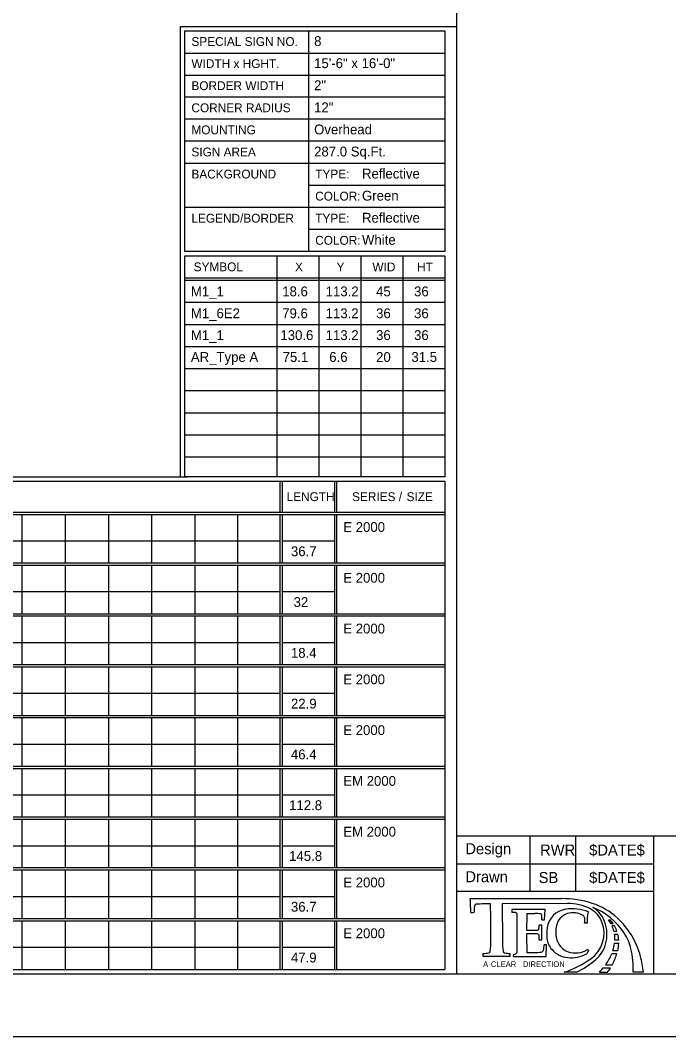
# Model space of a CAD drawing. Extents: x 2149934 to 2150188, y 145114 to 145238.
# Drawn here: x 2150112.6 to 2150146.6, y 145114.1 to 145167.4 of the extents above; entities that cross this region are included whole.
import ezdxf

# ---------------------------------------------------------------- set-up
doc = ezdxf.new("R2010")
doc.units = 0
for name, color, linetype in [('BORDER', 7, 'Continuous'), ('DATE', 7, 'Continuous'), ('GSSHT', 7, 'Continuous'), ('Level 1', 7, 'Continuous'), ('PDF', 7, 'Continuous'), ('TEC LOGO', 7, 'Continuous')]:
    doc.layers.add(name, color=color, linetype=linetype)

msp = doc.modelspace()

# ---------------------------------------------------------------- linework, layer by layer
at = {"layer": 'BORDER'}
for p, q in [((2150171.536, 145124.606), (2150135.447, 145124.606)), ((2150135.447, 145124.606), (2150135.447, 145117.388)), ((2150139.297, 145124.606), (2150139.297, 145121.719)), ((2150141.703, 145121.719), (2150141.703, 145124.606)), ((2150145.8, 145117.359), (2150145.8, 145124.577)), ((2150135.447, 145123.162), (2150145.8, 145123.162)), ((2150135.447, 145121.719), (2150145.8, 145121.719)), ((2150017.557, 145117.388), (2150171.536, 145117.388)), ((2150010.458, 145114.088), (2150174.061, 145114.088))]:
    msp.add_line(p, q, dxfattribs=at)
at = {"layer": 'Level 1'}
for p, q in [((2150135.447, 145216.512), (2150135.447, 145124.606)), ((2150120.969, 145167.112), (2150135.447, 145167.112)), ((2150127.694, 145166.88), (2150127.694, 145155.308)), ((2150121.201, 145165.721), (2150134.843, 145165.721)), ((2150121.201, 145164.561), (2150134.843, 145164.561)), ((2150121.201, 145163.425), (2150134.843, 145163.425)), ((2150121.201, 145162.265), (2150134.843, 145162.265)), ((2150121.201, 145161.106), (2150134.843, 145161.106)), ((2150121.201, 145159.946), (2150134.843, 145159.946)), ((2150127.694, 145158.787), (2150134.843, 145158.787)), ((2150121.201, 145157.627), (2150134.843, 145157.627)), ((2150127.694, 145156.468), (2150134.843, 145156.468)), ((2150121.201, 145143.476), (2150121.201, 145155.077)), ((2150121.201, 145155.077), (2150134.843, 145155.077)), ((2150126.031, 145155.071), (2150126.031, 145153.912)), ((2150128.234, 145155.071), (2150128.234, 145153.912)), ((2150130.437, 145155.071), (2150130.437, 145153.912)), ((2150132.64, 145155.071), (2150132.64, 145153.912)), ((2150134.843, 145155.077), (2150134.843, 145143.476)), ((2150121.201, 145153.912), (2150134.843, 145153.912)), ((2150121.201, 145153.796), (2150134.843, 145153.796)), ((2150126.031, 145153.912), (2150126.031, 145143.476)), ((2150128.234, 145153.912), (2150128.234, 145143.476)), ((2150130.437, 145153.912), (2150130.437, 145143.476)), ((2150132.64, 145153.912), (2150132.64, 145143.476)), ((2150121.201, 145152.636), (2150134.843, 145152.636)), ((2150121.201, 145151.477), (2150134.843, 145151.477)), ((2150121.201, 145150.317), (2150134.843, 145150.317)), ((2150121.201, 145149.158), (2150134.843, 145149.158)), ((2150121.201, 145147.998), (2150134.843, 145147.998)), ((2150121.201, 145146.839), (2150134.843, 145146.839)), ((2150121.201, 145145.679), (2150134.843, 145145.679)), ((2150121.201, 145144.52), (2150134.843, 145144.52)), ((2150076.316, 145143.476), (2150121.342, 145143.476)), ((2150076.548, 145143.244), (2150134.843, 145143.244)), ((2150134.843, 145143.476), (2150121.201, 145143.476)), ((2150126.185, 145143.244), (2150126.185, 145141.621)), ((2150126.301, 145143.244), (2150126.301, 145141.621)), ((2150129.048, 145143.244), (2150129.048, 145141.621)), ((2150129.164, 145143.244), (2150129.164, 145141.621)), ((2150134.843, 145143.244), (2150134.843, 145117.62)), ((2150076.548, 145141.621), (2150134.843, 145141.621)), ((2150076.548, 145141.505), (2150134.843, 145141.505)), ((2150112.654, 145141.505), (2150112.654, 145138.954)), ((2150114.927, 145141.505), (2150114.927, 145138.954)), ((2150117.199, 145141.505), (2150117.199, 145138.954)), ((2150119.449, 145141.505), (2150119.449, 145138.954)), ((2150121.721, 145141.505), (2150121.721, 145138.954)), ((2150123.97, 145141.505), (2150123.97, 145138.954)), ((2150126.185, 145141.505), (2150126.185, 145138.954)), ((2150126.301, 145141.505), (2150126.301, 145138.954)), ((2150129.048, 145141.505), (2150129.048, 145138.954)), ((2150129.164, 145141.505), (2150129.164, 145138.954)), ((2150076.548, 145140.114), (2150126.185, 145140.114)), ((2150126.301, 145140.114), (2150129.048, 145140.114)), ((2150076.548, 145138.954), (2150134.843, 145138.954)), ((2150076.548, 145138.838), (2150134.843, 145138.838)), ((2150112.654, 145138.838), (2150112.654, 145136.288)), ((2150114.927, 145138.838), (2150114.927, 145136.288)), ((2150117.199, 145138.838), (2150117.199, 145136.288)), ((2150119.449, 145138.838), (2150119.449, 145136.288)), ((2150121.721, 145138.838), (2150121.721, 145136.288)), ((2150123.97, 145138.838), (2150123.97, 145136.288)), ((2150126.185, 145138.838), (2150126.185, 145136.288)), ((2150126.301, 145138.838), (2150126.301, 145136.288)), ((2150129.048, 145138.838), (2150129.048, 145136.288)), ((2150129.164, 145138.838), (2150129.164, 145136.288)), ((2150076.548, 145137.447), (2150126.185, 145137.447)), ((2150126.301, 145137.447), (2150129.048, 145137.447)), ((2150076.548, 145136.288), (2150134.843, 145136.288)), ((2150076.548, 145136.172), (2150134.843, 145136.172)), ((2150112.654, 145136.172), (2150112.654, 145133.621)), ((2150114.927, 145136.172), (2150114.927, 145133.621)), ((2150117.199, 145136.172), (2150117.199, 145133.621)), ((2150119.449, 145136.172), (2150119.449, 145133.621)), ((2150121.721, 145136.172), (2150121.721, 145133.621)), ((2150123.97, 145136.172), (2150123.97, 145133.621)), ((2150126.185, 145136.172), (2150126.185, 145133.621)), ((2150126.301, 145136.172), (2150126.301, 145133.621)), ((2150129.048, 145136.172), (2150129.048, 145133.621)), ((2150129.164, 145136.172), (2150129.164, 145133.621)), ((2150076.548, 145134.78), (2150126.185, 145134.78)), ((2150126.301, 145134.78), (2150129.048, 145134.78)), ((2150076.548, 145133.621), (2150134.843, 145133.621)), ((2150076.548, 145133.505), (2150134.843, 145133.505)), ((2150112.654, 145133.505), (2150112.654, 145130.954)), ((2150114.927, 145133.505), (2150114.927, 145130.954)), ((2150117.199, 145133.505), (2150117.199, 145130.954)), ((2150119.449, 145133.505), (2150119.449, 145130.954)), ((2150121.721, 145133.505), (2150121.721, 145130.954)), ((2150123.97, 145133.505), (2150123.97, 145130.954)), ((2150126.185, 145133.505), (2150126.185, 145130.954)), ((2150126.301, 145133.505), (2150126.301, 145130.954)), ((2150129.048, 145133.505), (2150129.048, 145130.954)), ((2150129.164, 145133.505), (2150129.164, 145130.954)), ((2150076.548, 145132.113), (2150126.185, 145132.113)), ((2150126.301, 145132.113), (2150129.048, 145132.113)), ((2150076.548, 145130.954), (2150134.843, 145130.954)), ((2150076.548, 145130.838), (2150134.843, 145130.838)), ((2150112.654, 145130.838), (2150112.654, 145128.287)), ((2150114.927, 145130.838), (2150114.927, 145128.287)), ((2150117.199, 145130.838), (2150117.199, 145128.287)), ((2150119.449, 145130.838), (2150119.449, 145128.287)), ((2150121.721, 145130.838), (2150121.721, 145128.287)), ((2150123.97, 145130.838), (2150123.97, 145128.287)), ((2150126.185, 145130.838), (2150126.185, 145128.287)), ((2150126.301, 145130.838), (2150126.301, 145128.287)), ((2150129.048, 145130.838), (2150129.048, 145128.287)), ((2150129.164, 145130.838), (2150129.164, 145128.287)), ((2150076.548, 145129.447), (2150126.185, 145129.447)), ((2150126.301, 145129.447), (2150129.048, 145129.447)), ((2150076.548, 145128.287), (2150134.843, 145128.287)), ((2150076.548, 145128.171), (2150134.843, 145128.171)), ((2150112.654, 145128.171), (2150112.654, 145125.62)), ((2150114.927, 145128.171), (2150114.927, 145125.62)), ((2150117.199, 145128.171), (2150117.199, 145125.62)), ((2150119.449, 145128.171), (2150119.449, 145125.62)), ((2150121.721, 145128.171), (2150121.721, 145125.62)), ((2150123.97, 145128.171), (2150123.97, 145125.62)), ((2150126.185, 145128.171), (2150126.185, 145125.62)), ((2150126.301, 145128.171), (2150126.301, 145125.62)), ((2150129.048, 145128.171), (2150129.048, 145125.62)), ((2150129.164, 145128.171), (2150129.164, 145125.62)), ((2150076.548, 145126.78), (2150126.185, 145126.78)), ((2150126.301, 145126.78), (2150129.048, 145126.78)), ((2150076.548, 145125.62), (2150134.843, 145125.62)), ((2150076.548, 145125.504), (2150134.843, 145125.504)), ((2150112.654, 145125.504), (2150112.654, 145122.954)), ((2150114.927, 145125.504), (2150114.927, 145122.954)), ((2150117.199, 145125.504), (2150117.199, 145122.954)), ((2150119.449, 145125.504), (2150119.449, 145122.954)), ((2150121.721, 145125.504), (2150121.721, 145122.954)), ((2150123.97, 145125.504), (2150123.97, 145122.954)), ((2150126.185, 145125.504), (2150126.185, 145122.954)), ((2150126.301, 145125.504), (2150126.301, 145122.954)), ((2150129.048, 145125.504), (2150129.048, 145122.954)), ((2150129.164, 145125.504), (2150129.164, 145122.954)), ((2150076.548, 145124.113), (2150126.185, 145124.113)), ((2150126.301, 145124.113), (2150129.048, 145124.113)), ((2150134.843, 145122.954), (2150076.548, 145122.954)), ((2150076.548, 145122.838), (2150134.843, 145122.838)), ((2150112.654, 145122.838), (2150112.654, 145120.287)), ((2150114.927, 145122.838), (2150114.927, 145120.287)), ((2150117.199, 145122.838), (2150117.199, 145120.287)), ((2150119.449, 145122.838), (2150119.449, 145120.287)), ((2150121.721, 145122.838), (2150121.721, 145120.287)), ((2150123.97, 145122.838), (2150123.97, 145120.287)), ((2150126.185, 145122.838), (2150126.185, 145120.287)), ((2150126.301, 145122.838), (2150126.301, 145120.287)), ((2150129.048, 145122.838), (2150129.048, 145120.287)), ((2150129.164, 145122.838), (2150129.164, 145120.287)), ((2150076.548, 145121.446), (2150126.185, 145121.446)), ((2150126.301, 145121.446), (2150129.048, 145121.446)), ((2150076.548, 145120.287), (2150134.843, 145120.287)), ((2150076.548, 145120.171), (2150134.843, 145120.171)), ((2150112.654, 145120.171), (2150112.654, 145117.62)), ((2150114.927, 145120.171), (2150114.927, 145117.62)), ((2150117.199, 145120.171), (2150117.199, 145117.62)), ((2150119.449, 145120.171), (2150119.449, 145117.62)), ((2150121.721, 145120.171), (2150121.721, 145117.62)), ((2150123.97, 145120.171), (2150123.97, 145117.62)), ((2150126.185, 145120.171), (2150126.185, 145117.62)), ((2150126.301, 145120.171), (2150126.301, 145117.62)), ((2150129.048, 145120.171), (2150129.048, 145117.62)), ((2150129.164, 145120.171), (2150129.164, 145117.62)), ((2150076.548, 145118.779), (2150126.185, 145118.779)), ((2150126.301, 145118.779), (2150129.048, 145118.779)), ((2150076.548, 145117.62), (2150134.843, 145117.62))]:
    msp.add_line(p, q, dxfattribs=at)
msp.add_lwpolyline([(2150120.969, 145143.476), (2150120.969, 145167.112)], dxfattribs=at)
msp.add_lwpolyline([(2150121.201, 145166.88), (2150134.843, 145166.88), (2150134.843, 145155.308), (2150121.201, 145155.308)], close=True, dxfattribs=at)
at = {"layer": 'PDF'}
msp.add_lwpolyline([(2150010.458, 145114.088), (2150174.061, 145114.088), (2150174.061, 145219.948), (2150010.458, 145219.948)], close=True, dxfattribs=at)
at = {"layer": 'TEC LOGO'}
for p, q in [((2150136.163, 145121.335), (2150140.955, 145121.335)), ((2150141.264, 145121.082), (2150137.847, 145121.062)), ((2150137.238, 145121.058), (2150136.905, 145121.056)), ((2150137.847, 145121.062), (2150137.86, 145119.111)), ((2150138.352, 145120.759), (2150138.349, 145120.611)), ((2150140.106, 145120.759), (2150138.352, 145120.759)), ((2150139.134, 145120.555), (2150139.56, 145120.552)), ((2150140.07, 145120.219), (2150140.106, 145120.759)), ((2150139.925, 145120.219), (2150140.07, 145120.219)), ((2150142.3, 145120.043), (2150142.168, 145120.048)), ((2150142.307, 145120.354), (2150142.3, 145120.043)), ((2150143.414, 145120.213), (2150143.504, 145120.213)), ((2150143.669, 145120.008), (2150143.554, 145120.008)), ((2150139.925, 145119.934), (2150139.778, 145119.934)), ((2150139.925, 145119.172), (2150139.925, 145119.934)), ((2150143.731, 145119.909), (2150143.606, 145119.909)), ((2150143.709, 145119.627), (2150143.862, 145119.627)), ((2150139.785, 145119.172), (2150139.925, 145119.172)), ((2150143.74, 145119.471), (2150143.909, 145119.471)), ((2150143.743, 145118.997), (2150143.958, 145118.997)), ((2150143.957, 145119.151), (2150143.755, 145119.151)), ((2150136.856, 145118.3), (2150136.856, 145118.452)), ((2150138.255, 145118.452), (2150138.255, 145118.3)), ((2150140.175, 145118.91), (2150140.043, 145118.91)), ((2150140.159, 145118.3), (2150140.175, 145118.91)), ((2150142.374, 145118.62), (2150142.288, 145118.435)), ((2150142.324, 145118.657), (2150142.374, 145118.62)), ((2150143.86, 145118.438), (2150143.591, 145118.438)), ((2150143.903, 145118.595), (2150143.65, 145118.595)), ((2150138.255, 145118.3), (2150136.856, 145118.3)), ((2150138.439, 145118.399), (2150138.43, 145118.3)), ((2150138.43, 145118.3), (2150140.159, 145118.3)), ((2150141.747, 145117.467), (2150141.099, 145117.467)), ((2150142.942, 145117.467), (2150143.375, 145117.467)), ((2150143.52, 145117.689), (2150143.126, 145117.689)), ((2150143.264, 145117.867), (2150143.623, 145117.867)), ((2150145.252, 145117.467), (2150144.714, 145117.467))]:
    msp.add_line(p, q, dxfattribs=at)
for centre, radius, start, end in [((2150129.713, 145120.639), 6.487, 359.663, 6.1563), ((2150140.955, 145116.038), 5.297, 72.2522, 90), ((2150141.28, 145118.51), 2.573, 62.4303, 90.3367), ((2150141.492, 145117.716), 3.535, 47.2839, 72.2522), ((2150136.235, 145120.976), 0.377, 264.6321, 291.5899), ((2150142.861, 145120.639), 6.487, 178.5623, 180.1181), ((2150137.218, 145120.781), 0.843, 167.5337, 178.5623), ((2150136.49, 145120.942), 0.0962, 94.698, 167.5337), ((2150136.937, 145115.493), 5.563, 90.3367, 94.698), ((2150046.46, 145119.478), 90.791, 359.77628, 0.99712), ((2150138.383, 145119.475), 1.137, 80.6874, 91.7186), ((2150138.555, 145120.525), 0.0722, 1.4011, 80.6874), ((2150222.857, 145119.533), 83.729, 179.30064, 179.90313), ((2150139.538, 145117.558), 2.995, 83.8831, 89.5816), ((2150141.338, 145119.635), 1.149, 97.9231, 172.0344), ((2150141.512, 145119.746), 0.839, 107.7088, 167.9528), ((2150141.514, 145118.371), 2.426, 69.3982, 97.9231), ((2150141.562, 145119.589), 1.004, 58.2676, 107.7088), ((2150143.117, 145120.335), 0.81, 157.7575, 178.6366), ((2150141.873, 145119.647), 1.289, 20.6867, 62.4303), ((2150141.269, 145117.57), 3.562, 32.9982, 68.0651), ((2150141.873, 145119.647), 1.426, 26.3065, 59.3722), ((2150097.794, 145119.528), 40.845, 358.5952, 1.4011), ((2150139.849, 145120.463), 0.0722, 5.4112, 83.8831), ((2150138.327, 145120.319), 1.601, 356.4205, 5.4112), ((2150141.997, 145120.293), 0.176, 2.4202, 58.2676), ((2150140.098, 145120.213), 2.077, 355.4457, 2.4202), ((2150141.537, 145119.52), 1.649, 305.1645, 20.6867), ((2150141.484, 145119.455), 1.86, 348.2376, 26.3065), ((2150142.22, 145119.245), 1.536, 29.7365, 39.0219), ((2150142.29, 145119.068), 1.669, 34.2695, 43.3207), ((2150141.052, 145117.24), 4.183, 14.7043, 47.2839), ((2150139.363, 145128.515), 8.844, 268.4788, 271.5206), ((2150139.362, 145110.642), 8.844, 88.4794, 91.5212), ((2150222.857, 145119.533), 83.729, 180.03409, 180.69936), ((2150139.572, 145120.641), 0.967, 271.5206, 277.9096), ((2150139.571, 145118.517), 0.967, 81.2846, 88.4794), ((2150139.695, 145119.755), 0.0722, 277.9096, 349.9583), ((2150139.707, 145119.401), 0.0722, 5.6885, 81.2846), ((2150138.932, 145119.89), 0.847, 349.9583, 3.0005), ((2150142.345, 145119.494), 2.166, 172.0344, 186.3105), ((2150142.25, 145119.588), 1.594, 167.9528, 193.0838), ((2150142.22, 145119.245), 1.536, 14.3628, 25.5725), ((2150142.29, 145119.068), 1.669, 19.5618, 30.2542), ((2150142.146, 145118.139), 2.517, 12.951, 32.9982), ((2150132.45, 145119.143), 4.801, 353.2347, 359.7763), ((2150142.661, 145119.143), 4.801, 180.3775, 186.7653), ((2150138.141, 145119.245), 1.646, 357.4607, 5.6885), ((2150141.269, 145119.375), 1.083, 186.3105, 221.5776), ((2150141.645, 145119.448), 0.973, 193.0838, 228.7889), ((2150141.651, 145119.42), 1.689, 310.5997, 348.2376), ((2150141.804, 145119.231), 1.952, 341.0487, 353.1199), ((2150142.22, 145119.245), 1.536, 2.0409, 8.4283), ((2150141.804, 145119.231), 1.952, 357.6694, 2.0409), ((2150142.049, 145119.055), 1.911, 346.0491, 358.2376), ((2150142.29, 145119.068), 1.669, 2.8667, 13.9687), ((2150142.049, 145119.055), 1.911, 2.8951, 2.9107), ((2150136.867, 145119.381), 0.929, 269.3409, 287.8364), ((2150137.122, 145118.588), 0.0962, 287.8364, 353.2347), ((2150137.989, 145118.588), 0.0962, 186.7653, 252.1636), ((2150138.244, 145119.381), 0.929, 252.1636, 270.6591), ((2150138.412, 145118.712), 0.314, 274.8598, 303.0633), ((2150138.531, 145118.529), 0.0962, 303.0633, 358.5952), ((2150139.369, 145127.352), 8.844, 268.4788, 273.4332), ((2150139.893, 145118.62), 0.0962, 273.4332, 326.9687), ((2150139.753, 145118.711), 0.263, 326.9687, 342.6077), ((2150139.168, 145118.894), 0.876, 342.6077, 1.0782), ((2150141.404, 145119.495), 1.263, 221.5776, 264.5103), ((2150141.577, 145119.37), 0.87, 228.7889, 251.3711), ((2150141.454, 145120.022), 1.792, 264.5103, 297.7193), ((2150141.691, 145119.707), 1.226, 251.3711, 301.0817), ((2150141.152, 145119.455), 2.643, 323.1081, 337.382), ((2150140.843, 145119.355), 3.152, 331.8459, 343.1036), ((2150141.152, 145119.455), 2.643, 341.0109, 341.0487), ((2150140.843, 145119.355), 3.152, 346.0548, 346.0603), ((2150140.037, 145117.654), 4.681, 357.7052, 12.951), ((2150139.346, 145122.63), 5.453, 288.7522, 305.1645), ((2150139.464, 145121.971), 5.05, 296.8707, 310.5997), ((2150139.621, 145116.864), 5.663, 6.1104, 14.7043), ((2150137.249, 145122.384), 7.522, 319.179, 321.3834), ((2150137.249, 145122.384), 7.522, 323.0973, 323.1081), ((2150137.725, 145121.305), 6.831, 325.8118, 328.04), ((2150140.843, 145119.355), 3.152, 327.9791, 328.0787)]:
    msp.add_arc(centre, radius, start, end, dxfattribs=at)

# ---------------------------------------------------------------- texts
at = {"layer": 'BORDER'}
for s, p in [('Design', (2150135.913, 145123.665)), ('RWR', (2150139.833, 145123.596)), ('Drawn', (2150135.913, 145122.195)), ('SB ', (2150139.76, 145122.152))]:
    msp.add_text(s, height=0.5774, dxfattribs=at).set_placement(p)
at = {"layer": 'DATE'}
for p in [(2150142.406, 145123.595), (2150142.406, 145122.152)]:
    msp.add_text('$DATE$', height=0.5774, dxfattribs=at).set_placement(p)
at = {"layer": 'GSSHT'}
for s, height, p in [('8', 0.517, (2150127.983, 145166.087)), ('Overhead', 0.5165, (2150127.983, 145161.451))]:
    msp.add_text(s, height=height, dxfattribs=at).set_placement(p)
at = {"layer": 'Level 1'}
for s, height, p in [('SPECIAL SIGN NO.', 0.46374, (2150121.549, 145166.092)), ('WIDTH x HGHT.', 0.46374, (2150121.549, 145164.932)), ('15\'-6" x 16\'-0"', 0.51652, (2150127.983, 145164.928)), ('2"', 0.5165, (2150127.983, 145163.769)), ('BORDER WIDTH', 0.46374, (2150121.549, 145163.773)), ('CORNER RADIUS', 0.46374, (2150121.549, 145162.613)), ('12"', 0.5165, (2150127.983, 145162.61)), ('MOUNTING', 0.4637, (2150121.549, 145161.454)), ('SIGN AREA', 0.4638, (2150121.549, 145160.294)), ('287.0 Sq.Ft.', 0.51652, (2150127.983, 145160.292)), ('BACKGROUND', 0.4637, (2150121.549, 145159.135)), ('TYPE:', 0.4637, (2150128.042, 145159.135)), ('Reflective', 0.5165, (2150130.494, 145159.133)), ('COLOR:', 0.4637, (2150128.042, 145157.975)), ('Green', 0.5165, (2150130.494, 145157.974)), ('Reflective', 0.5165, (2150130.494, 145156.815)), ('LEGEND/BORDER', 0.46374, (2150121.549, 145156.816)), ('TYPE:', 0.4637, (2150128.042, 145156.816)), ('COLOR:', 0.4637, (2150128.042, 145155.656)), ('White', 0.5165, (2150130.494, 145155.656)), ('SYMBOL', 0.4637, (2150121.665, 145154.265)), ('X', 0.464, (2150126.981, 145154.259)), ('Y', 0.464, (2150129.161, 145154.259)), ('WID', 0.4637, (2150131.04, 145154.259)), ('HT', 0.4637, (2150133.382, 145154.259)), ('M1_1', 0.5165, (2150121.52, 145152.949)), ('18.6', 0.5165, (2150126.31, 145152.949)), ('113.2', 0.5165, (2150128.589, 145152.949)), ('45', 0.5165, (2150131.233, 145152.949)), ('36', 0.5165, (2150133.225, 145152.949)), ('M1_6E2', 0.5165, (2150121.52, 145151.801)), ('79.6', 0.5165, (2150126.31, 145151.801)), ('113.2', 0.5165, (2150128.589, 145151.801)), ('36', 0.5165, (2150131.233, 145151.801)), ('36', 0.5165, (2150133.225, 145151.801)), ('M1_1', 0.5165, (2150121.52, 145150.653)), ('130.6', 0.5165, (2150126.216, 145150.653)), ('113.2', 0.5165, (2150128.589, 145150.653)), ('36', 0.5165, (2150131.233, 145150.653)), ('36', 0.5165, (2150133.225, 145150.653)), ('AR_Type A', 0.5165, (2150121.52, 145149.506)), ('75.1', 0.5165, (2150126.331, 145149.506)), ('6.6', 0.5165, (2150128.777, 145149.506)), ('20', 0.5165, (2150131.233, 145149.506)), ('31.5', 0.5165, (2150133.084, 145149.506)), ('LENGTH', 0.4638, (2150126.541, 145142.201)), ('LENGTH', 0.4638, (2150126.541, 145142.201)), ('SERIES /', 0.4638, (2150129.975, 145142.201)), ('SIZE', 0.4638, (2150132.832, 145142.201)), ('E 2000', 0.5165, (2150129.512, 145140.582)), ('36.7', 0.5165, (2150126.768, 145139.307)), ('E 2000', 0.5165, (2150129.512, 145137.916)), ('32', 0.5165, (2150126.909, 145136.642)), ('E 2000', 0.5165, (2150129.512, 145135.251)), ('18.4', 0.5165, (2150126.766, 145133.976)), ('E 2000', 0.5165, (2150129.512, 145132.585)), ('22.9', 0.5165, (2150126.768, 145131.311)), ('E 2000', 0.5165, (2150129.512, 145129.92)), ('46.4', 0.5165, (2150126.766, 145128.645)), ('EM 2000', 0.5165, (2150129.512, 145127.255)), ('112.8', 0.5165, (2150126.674, 145125.98)), ('EM 2000', 0.5165, (2150129.512, 145124.589)), ('145.8', 0.5165, (2150126.674, 145123.314)), ('E 2000', 0.5165, (2150129.512, 145121.924)), ('36.7', 0.5165, (2150126.768, 145120.649)), ('E 2000', 0.5165, (2150129.512, 145119.258)), ('47.9', 0.5165, (2150126.768, 145117.984))]:
    msp.add_text(s, height=height, dxfattribs=at).set_placement(p)
at = {"layer": 'TEC LOGO'}
for s, height, p in [('A', 0.298, (2150136.847, 145117.742)), ('CLEAR', 0.2983, (2150137.254, 145117.742)), ('DIRECTION', 0.2983, (2150138.933, 145117.742))]:
    msp.add_text(s, height=height, dxfattribs=at).set_placement(p)

doc.saveas('drawing.dxf')
